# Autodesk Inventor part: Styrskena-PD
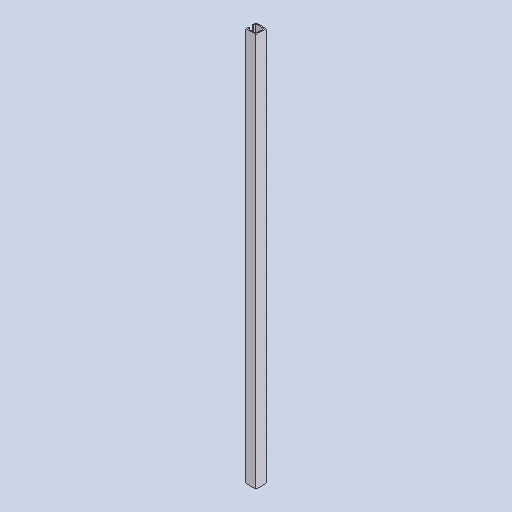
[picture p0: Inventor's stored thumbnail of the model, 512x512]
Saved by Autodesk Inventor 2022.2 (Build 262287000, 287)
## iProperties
Created: 2019-06
Part Number: Styrskena-PD
Material: Aluminum 6061, Welded
Document SubType Name: Modeling
Designer: cl
Density: 2.7 g/cm^3
Appearance: Weld - Aluminum
Author: cl
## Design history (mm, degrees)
sketch "Sketch1"
  geometry: L1 (0, 0)-(50, 0); L2 (50, 0)-(50, -15); L3 (50, -35)-(50, -50); L4 (50, -50)-(0, -50); L5 (0, -50)-(0, 0); L6 (50, -15)-(45, -15); L7 (45, -15)-(45, -5); L8 (45, -5)-(5, -5); L9 (5, -5)-(5, -45); L10 (5, -45)-(45, -45); L11 (45, -45)-(45, -35); L12 (45, -35)-(50, -35)
  constraints: 24 end point, 7 perpendicular, 4 point on line, 2 horizontal, 1 parallel
  dimensions: "d0" = 50 distance of L1.start L1.end; "d1" = 15 distance of L1.end L2.end; "d2" = 15 distance of L3.start L3.end; "d3" = 50 distance of L4.end L1.start; "d5" = 5 distance of L2.end L6.end; "d6" = 10 distance of L6.end L7.end; "d7" = 10 distance of L10.end L11.end; "d9" = 5 distance between parallel lines of L5 L9
extrude "Extrusion1" new body sketch "Sketch1" distance "d10" = 1965 (computed from BladBredd); taper "d11" = 0 deg
body "Solid1"
other parameters: "BladBredd" = 987.5, "Fönsterhöjd" = 862, "Blad2" = 1012.5, "Blad3" = 0, "Blad4" = 0, "Blad5" = 1012.5, "Blad6" = 2025, "MGJ12Djup" = 0, "MGJ12Bredd" = 0, "MGJ2Djup" = 0, "MGJ2Bredd" = 5012.5, "MGJ56Djup" = 0, "MGJ56Bredd" = 0, "MGJ23Djup" = 48, "MGJ45Djup" = 48, "GarageRegel5" = 0, "GarageRegel6" = 0
